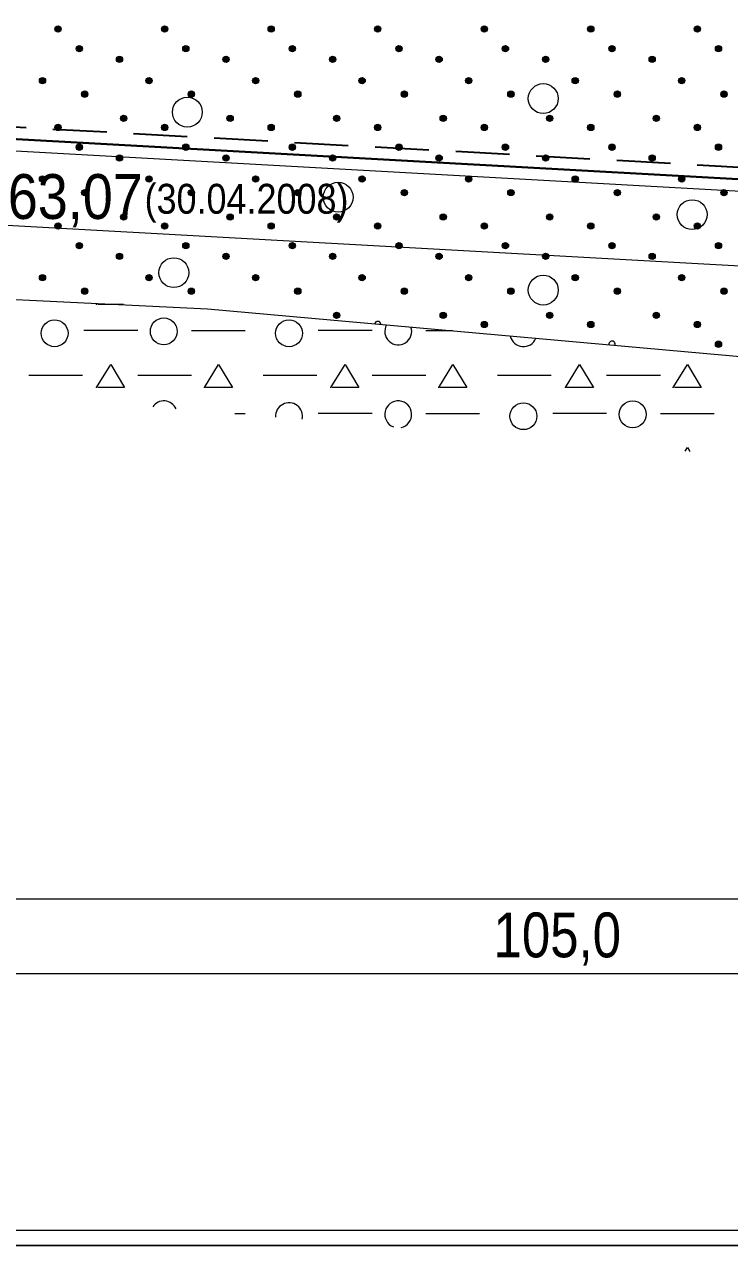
# Model space of a CAD drawing. Extents: x 640104 to 640970, y 6442278 to 6442689.
# Drawn here: x 640426.8 to 640474.1, y 6442282.5 to 6442364.3 of the extents above; entities that cross this region are included whole.
import ezdxf
from ezdxf.enums import TextEntityAlignment as Align

# ---------------------------------------------------------------- set-up
doc = ezdxf.new("R2010")
doc.units = 0
doc.header["$LTSCALE"] = 1.2
doc.linetypes.add('MEDIUM_DASHED', pattern=[4.5, 3, -1.5])
for name, color, linetype, lineweight in [('30', 7, 'Continuous', 13), ('31', 7, 'Continuous', 13), ('34', 7, 'Continuous', 25), ('35', 7, 'Continuous', 35), ('44', 7, 'Continuous', 13), ('46', 7, 'Continuous', 13), ('47', 7, 'Continuous', 13), ('50', 7, 'Continuous', 13)]:
    doc.layers.add(name, color=color, linetype=linetype, lineweight=lineweight)

msp = doc.modelspace()

# ---------------------------------------------------------------- hatches: boundary and pattern name
at = {"layer": '44'}
for points in [[(640429.308, 6442364.001, 1), (640428.888, 6442364.001, 1)], [(640436.441, 6442364.001, 1), (640436.021, 6442364.001, 1)], [(640443.574, 6442364.001, 1), (640443.154, 6442364.001, 1)], [(640450.707, 6442364.001, 1), (640450.287, 6442364.001, 1)], [(640457.84, 6442364.001, 1), (640457.42, 6442364.001, 1)], [(640464.973, 6442364.001, 1), (640464.553, 6442364.001, 1)], [(640472.106, 6442364.001, 1), (640471.686, 6442364.001, 1)], [(640430.727, 6442362.679, 1), (640430.307, 6442362.679, 1)], [(640437.86, 6442362.679, 1), (640437.44, 6442362.679, 1)], [(640444.993, 6442362.679, 1), (640444.573, 6442362.679, 1)], [(640452.126, 6442362.679, 1), (640451.706, 6442362.679, 1)], [(640459.259, 6442362.679, 1), (640458.839, 6442362.679, 1)], [(640466.392, 6442362.679, 1), (640465.972, 6442362.679, 1)], [(640473.525, 6442362.679, 1), (640473.105, 6442362.679, 1)], [(640433.419, 6442361.963, 1), (640432.999, 6442361.963, 1)], [(640440.552, 6442361.963, 1), (640440.132, 6442361.963, 1)], [(640447.685, 6442361.963, 1), (640447.265, 6442361.963, 1)], [(640454.818, 6442361.963, 1), (640454.398, 6442361.963, 1)], [(640461.951, 6442361.963, 1), (640461.531, 6442361.963, 1)], [(640469.084, 6442361.963, 1), (640468.664, 6442361.963, 1)], [(640428.264, 6442360.544, 1), (640427.844, 6442360.544, 1)], [(640435.397, 6442360.544, 1), (640434.977, 6442360.544, 1)], [(640442.53, 6442360.544, 1), (640442.11, 6442360.544, 1)], [(640449.663, 6442360.544, 1), (640449.243, 6442360.544, 1)], [(640456.796, 6442360.544, 1), (640456.376, 6442360.544, 1)], [(640463.929, 6442360.544, 1), (640463.509, 6442360.544, 1)], [(640471.062, 6442360.544, 1), (640470.642, 6442360.544, 1)], [(640431.091, 6442359.636, 1), (640430.671, 6442359.636, 1)], [(640438.224, 6442359.636, 1), (640437.804, 6442359.636, 1)], [(640445.357, 6442359.636, 1), (640444.937, 6442359.636, 1)], [(640452.49, 6442359.636, 1), (640452.07, 6442359.636, 1)], [(640459.623, 6442359.636, 1), (640459.203, 6442359.636, 1)], [(640466.756, 6442359.636, 1), (640466.336, 6442359.636, 1)], [(640473.889, 6442359.636, 1), (640473.469, 6442359.636, 1)], [(640433.693, 6442358.01, 1), (640433.273, 6442358.01, 1)], [(640440.826, 6442358.01, 1), (640440.406, 6442358.01, 1)], [(640447.959, 6442358.01, 1), (640447.539, 6442358.01, 1)], [(640455.092, 6442358.01, 1), (640454.672, 6442358.01, 1)], [(640462.225, 6442358.01, 1), (640461.805, 6442358.01, 1)], [(640469.358, 6442358.01, 1), (640468.938, 6442358.01, 1)], [(640429.308, 6442357.405, 1), (640428.888, 6442357.405, 1)], [(640436.441, 6442357.405, 1), (640436.021, 6442357.405, 1)], [(640443.574, 6442357.405, 1), (640443.154, 6442357.405, 1)], [(640450.707, 6442357.405, 1), (640450.287, 6442357.405, 1)], [(640457.84, 6442357.405, 1), (640457.42, 6442357.405, 1)], [(640464.973, 6442357.405, 1), (640464.553, 6442357.405, 1)], [(640472.106, 6442357.405, 1), (640471.686, 6442357.405, 1)], [(640430.727, 6442356.083, 1), (640430.307, 6442356.083, 1)], [(640433.419, 6442355.367, 1), (640432.999, 6442355.367, 1)], [(640437.86, 6442356.083, 1), (640437.44, 6442356.083, 1)], [(640440.552, 6442355.367, 1), (640440.132, 6442355.367, 1)], [(640444.993, 6442356.083, 1), (640444.573, 6442356.083, 1)], [(640447.685, 6442355.367, 1), (640447.265, 6442355.367, 1)], [(640452.126, 6442356.083, 1), (640451.706, 6442356.083, 1)], [(640454.818, 6442355.367, 1), (640454.398, 6442355.367, 1)], [(640459.259, 6442356.083, 1), (640458.839, 6442356.083, 1)], [(640461.951, 6442355.367, 1), (640461.531, 6442355.367, 1)], [(640466.392, 6442356.083, 1), (640465.972, 6442356.083, 1)], [(640469.084, 6442355.367, 1), (640468.664, 6442355.367, 1)], [(640473.525, 6442356.083, 1), (640473.105, 6442356.083, 1)], [(640428.264, 6442353.948, 1), (640427.844, 6442353.948, 1)], [(640435.397, 6442353.948, 1), (640434.977, 6442353.948, 1)], [(640442.53, 6442353.948, 1), (640442.11, 6442353.948, 1)], [(640449.663, 6442353.948, 1), (640449.243, 6442353.948, 1)], [(640456.796, 6442353.948, 1), (640456.376, 6442353.948, 1)], [(640463.929, 6442353.948, 1), (640463.509, 6442353.948, 1)], [(640471.062, 6442353.948, 1), (640470.642, 6442353.948, 1)], [(640431.091, 6442353.04, 1), (640430.671, 6442353.04, 1)], [(640438.224, 6442353.04, 1), (640437.804, 6442353.04, 1)], [(640445.357, 6442353.04, 1), (640444.937, 6442353.04, 1)], [(640452.49, 6442353.04, 1), (640452.07, 6442353.04, 1)], [(640459.623, 6442353.04, 1), (640459.203, 6442353.04, 1)], [(640466.756, 6442353.04, 1), (640466.336, 6442353.04, 1)], [(640473.889, 6442353.04, 1), (640473.469, 6442353.04, 1)], [(640433.693, 6442351.414, 1), (640433.273, 6442351.414, 1)], [(640440.826, 6442351.414, 1), (640440.406, 6442351.414, 1)], [(640447.959, 6442351.414, 1), (640447.539, 6442351.414, 1)], [(640455.092, 6442351.414, 1), (640454.672, 6442351.414, 1)], [(640462.225, 6442351.414, 1), (640461.805, 6442351.414, 1)], [(640469.358, 6442351.414, 1), (640468.938, 6442351.414, 1)], [(640429.308, 6442350.809, 1), (640428.888, 6442350.809, 1)], [(640436.441, 6442350.809, 1), (640436.021, 6442350.809, 1)], [(640443.574, 6442350.809, 1), (640443.154, 6442350.809, 1)], [(640450.707, 6442350.809, 1), (640450.287, 6442350.809, 1)], [(640457.84, 6442350.809, 1), (640457.42, 6442350.809, 1)], [(640464.973, 6442350.809, 1), (640464.553, 6442350.809, 1)], [(640472.106, 6442350.809, 1), (640471.686, 6442350.809, 1)], [(640430.727, 6442349.487, 1), (640430.307, 6442349.487, 1)], [(640433.419, 6442348.771, 1), (640432.999, 6442348.771, 1)], [(640437.86, 6442349.487, 1), (640437.44, 6442349.487, 1)], [(640440.552, 6442348.771, 1), (640440.132, 6442348.771, 1)], [(640444.993, 6442349.487, 1), (640444.573, 6442349.487, 1)], [(640447.685, 6442348.771, 1), (640447.265, 6442348.771, 1)], [(640452.126, 6442349.487, 1), (640451.706, 6442349.487, 1)], [(640454.818, 6442348.771, 1), (640454.398, 6442348.771, 1)], [(640459.259, 6442349.487, 1), (640458.839, 6442349.487, 1)], [(640461.951, 6442348.771, 1), (640461.531, 6442348.771, 1)], [(640466.392, 6442349.487, 1), (640465.972, 6442349.487, 1)], [(640469.084, 6442348.771, 1), (640468.664, 6442348.771, 1)], [(640473.525, 6442349.487, 1), (640473.105, 6442349.487, 1)], [(640428.264, 6442347.352, 1), (640427.844, 6442347.352, 1)], [(640435.397, 6442347.352, 1), (640434.977, 6442347.352, 1)], [(640442.53, 6442347.352, 1), (640442.11, 6442347.352, 1)], [(640449.663, 6442347.352, 1), (640449.243, 6442347.352, 1)], [(640456.796, 6442347.352, 1), (640456.376, 6442347.352, 1)], [(640463.929, 6442347.352, 1), (640463.509, 6442347.352, 1)], [(640471.062, 6442347.352, 1), (640470.642, 6442347.352, 1)], [(640431.091, 6442346.444, 1), (640430.671, 6442346.444, 1)], [(640438.224, 6442346.444, 1), (640437.804, 6442346.444, 1)], [(640445.357, 6442346.444, 1), (640444.937, 6442346.444, 1)], [(640452.49, 6442346.444, 1), (640452.07, 6442346.444, 1)], [(640459.623, 6442346.444, 1), (640459.203, 6442346.444, 1)], [(640466.756, 6442346.444, 1), (640466.336, 6442346.444, 1)], [(640473.889, 6442346.444, 1), (640473.469, 6442346.444, 1)], [(640447.959, 6442344.818, 1), (640447.539, 6442344.818, 1)], [(640455.092, 6442344.818, 1), (640454.672, 6442344.818, 1)], [(640462.225, 6442344.818, 1), (640461.805, 6442344.818, 1)], [(640469.358, 6442344.818, 1), (640468.938, 6442344.818, 1)], [(640457.84, 6442344.213, 1), (640457.42, 6442344.213, 1)], [(640464.973, 6442344.213, 1), (640464.553, 6442344.213, 1)], [(640472.106, 6442344.213, 1), (640471.686, 6442344.213, 1)], [(640473.525, 6442342.891, 1), (640473.105, 6442342.891, 1)]]:
    msp.add_hatch(color=256, dxfattribs=at).paths.add_polyline_path(points)

# ---------------------------------------------------------------- linework, layer by layer
at = {"layer": '30'}
for p, q in [((640112.44, 6442305.75), (640578.08, 6442305.75)), ((640112.44, 6442300.75), (640578.08, 6442300.75))]:
    msp.add_line(p, q, dxfattribs=at)
at = {"layer": '31'}
msp.add_lwpolyline([(640139.08, 6442391.74), (640152, 6442391.74), (640184.83, 6442387.53), (640224.44, 6442383.27), (640230.93, 6442382.67), (640242.81, 6442381.6), (640246.59, 6442379.93), (640268.17, 6442370.27), (640295.32, 6442359.75), (640299.34, 6442358.9), (640322.09, 6442356.12), (640340.84, 6442354.22), (640374.54, 6442350.71), (640388.93, 6442348.78), (640409.14, 6442347), (640414.32, 6442346.47), (640439.11, 6442345.27), (640478.03, 6442341.77)], dxfattribs=at)
at = {"layer": '34', "lineweight": 13}
msp.add_lwpolyline([(640577.98, 6442339.23), (640519.43, 6442345.64), (640414.37, 6442351.46), (640348.88, 6442353.33)], dxfattribs=at)
at = {"layer": '35', "linetype": 'MEDIUM_DASHED'}
msp.add_lwpolyline([(640518.62, 6442352.3), (640414.65, 6442358.06), (640295.64, 6442361.35)], dxfattribs=at)
at = {"layer": '35', "lineweight": 40}
msp.add_lwpolyline([(640518.52, 6442351.5), (640414.61, 6442357.26), (640295.48, 6442360.55)], dxfattribs=at)
at = {"layer": '35', "lineweight": 13}
msp.add_lwpolyline([(640519.42, 6442350.65), (640414.58, 6442356.46), (640295.32, 6442359.75)], dxfattribs=at)
at = {"layer": '44'}
for centre in [(640429.098, 6442364.001), (640436.231, 6442364.001), (640443.364, 6442364.001), (640450.497, 6442364.001), (640457.63, 6442364.001), (640464.763, 6442364.001), (640471.896, 6442364.001), (640430.517, 6442362.679), (640437.65, 6442362.679), (640444.783, 6442362.679), (640451.916, 6442362.679), (640459.049, 6442362.679), (640466.182, 6442362.679), (640473.315, 6442362.679), (640433.209, 6442361.963), (640440.342, 6442361.963), (640447.475, 6442361.963), (640454.608, 6442361.963), (640461.741, 6442361.963), (640468.874, 6442361.963), (640428.054, 6442360.544), (640435.187, 6442360.544), (640442.32, 6442360.544), (640449.453, 6442360.544), (640456.586, 6442360.544), (640463.719, 6442360.544), (640470.852, 6442360.544), (640430.881, 6442359.636), (640438.014, 6442359.636), (640445.147, 6442359.636), (640452.28, 6442359.636), (640459.413, 6442359.636), (640466.546, 6442359.636), (640473.679, 6442359.636), (640433.483, 6442358.01), (640440.616, 6442358.01), (640447.749, 6442358.01), (640454.882, 6442358.01), (640462.015, 6442358.01), (640469.148, 6442358.01), (640429.098, 6442357.405), (640436.231, 6442357.405), (640443.364, 6442357.405), (640450.497, 6442357.405), (640457.63, 6442357.405), (640464.763, 6442357.405), (640471.896, 6442357.405), (640430.517, 6442356.083), (640433.209, 6442355.367), (640437.65, 6442356.083), (640440.342, 6442355.367), (640444.783, 6442356.083), (640447.475, 6442355.367), (640451.916, 6442356.083), (640454.608, 6442355.367), (640459.049, 6442356.083), (640461.741, 6442355.367), (640466.182, 6442356.083), (640468.874, 6442355.367), (640473.315, 6442356.083), (640428.054, 6442353.948), (640435.187, 6442353.948), (640442.32, 6442353.948), (640449.453, 6442353.948), (640456.586, 6442353.948), (640463.719, 6442353.948), (640470.852, 6442353.948), (640430.881, 6442353.04), (640438.014, 6442353.04), (640445.147, 6442353.04), (640452.28, 6442353.04), (640459.413, 6442353.04), (640466.546, 6442353.04), (640473.679, 6442353.04), (640433.483, 6442351.414), (640440.616, 6442351.414), (640447.749, 6442351.414), (640454.882, 6442351.414), (640462.015, 6442351.414), (640469.148, 6442351.414), (640429.098, 6442350.809), (640436.231, 6442350.809), (640443.364, 6442350.809), (640450.497, 6442350.809), (640457.63, 6442350.809), (640464.763, 6442350.809), (640471.896, 6442350.809), (640430.517, 6442349.487), (640433.209, 6442348.771), (640437.65, 6442349.487), (640440.342, 6442348.771), (640444.783, 6442349.487), (640447.475, 6442348.771), (640451.916, 6442349.487), (640454.608, 6442348.771), (640459.049, 6442349.487), (640461.741, 6442348.771), (640466.182, 6442349.487), (640468.874, 6442348.771), (640473.315, 6442349.487), (640428.054, 6442347.352), (640435.187, 6442347.352), (640442.32, 6442347.352), (640449.453, 6442347.352), (640456.586, 6442347.352), (640463.719, 6442347.352), (640470.852, 6442347.352), (640430.881, 6442346.444), (640438.014, 6442346.444), (640445.147, 6442346.444), (640452.28, 6442346.444), (640459.413, 6442346.444), (640466.546, 6442346.444), (640473.679, 6442346.444), (640447.749, 6442344.818), (640454.882, 6442344.818), (640462.015, 6442344.818), (640469.148, 6442344.818), (640457.63, 6442344.213), (640464.763, 6442344.213), (640471.896, 6442344.213), (640473.315, 6442342.891)]:
    msp.add_circle(centre, 0.21, dxfattribs=at)
for centre, start, end in [((640450.497, 6442344.213), 3.35441, 166.38326), ((640466.182, 6442342.891), 339.68393, 190.05373)]:
    msp.add_arc(centre, 0.21, start, end, dxfattribs=at)
at = {"layer": '46'}
for p, q in [((640433.48, 6442345.54), (640431.75, 6442345.55)), ((640434.43, 6442343.8), (640430.83, 6442343.8)), ((640441.63, 6442343.79), (640438.03, 6442343.79)), ((640450.12, 6442343.8), (640446.52, 6442343.8)), ((640455.5, 6442343.79), (640453.72, 6442343.79)), ((640430.73, 6442340.8), (640427.13, 6442340.8)), ((640438.03, 6442340.8), (640434.43, 6442340.8)), ((640446.43, 6442340.8), (640442.83, 6442340.8)), ((640453.72, 6442340.8), (640450.12, 6442340.8)), ((640462.12, 6442340.8), (640458.52, 6442340.8)), ((640469.42, 6442340.8), (640465.82, 6442340.8)), ((640441.63, 6442338.24), (640440.93, 6442338.24)), ((640450.12, 6442338.25), (640446.52, 6442338.25)), ((640457.32, 6442338.24), (640453.72, 6442338.24)), ((640465.82, 6442338.25), (640462.22, 6442338.25)), ((640473.02, 6442338.24), (640469.42, 6442338.24))]:
    msp.add_line(p, q, dxfattribs=at)
for points in [[(640431.67, 6442345.53), (640431.67, 6442345.55), (640431.72, 6442345.63)], [(640431.67, 6442339.97), (640431.67, 6442340), (640432.62, 6442341.53), (640433.55, 6442339.99), (640431.75, 6442340)], [(640438.89, 6442339.97), (640438.89, 6442340), (640439.84, 6442341.53), (640440.77, 6442339.99), (640438.97, 6442340)], [(640447.36, 6442339.97), (640447.37, 6442340), (640448.31, 6442341.53), (640449.24, 6442339.99), (640447.44, 6442340)], [(640454.58, 6442339.97), (640454.59, 6442340), (640455.53, 6442341.53), (640456.46, 6442339.99), (640454.66, 6442340)], [(640463.06, 6442339.97), (640463.06, 6442340), (640464.01, 6442341.53), (640464.94, 6442339.99), (640463.14, 6442340)], [(640470.28, 6442339.97), (640470.28, 6442340), (640471.23, 6442341.53), (640472.16, 6442339.99), (640470.36, 6442340)], [(640471.08, 6442335.73), (640471.23, 6442335.97), (640471.39, 6442335.7)]]:
    msp.add_lwpolyline(points, dxfattribs=at)
for centre in [(640428.864, 6442343.626), (640436.177, 6442343.748), (640444.559, 6442343.626), (640460.254, 6442338.072), (640467.567, 6442338.194)]:
    msp.add_circle(centre, 0.9, dxfattribs=at)
for centre, start, end in [((640451.872, 6442343.748), 150.56178, 19.17589), ((640460.254, 6442343.626), 191.49631, 338.24136), ((640436.177, 6442338.194), 24.57571, 145.89701), ((640444.559, 6442338.072), 346.71377, 183.75895), ((640451.872, 6442338.194), 281.84927, 248.62344)]:
    msp.add_arc(centre, 0.9, start, end, dxfattribs=at)
at = {"layer": '47'}
for centre in [(640461.581, 6442359.338), (640437.752, 6442358.431), (640447.853, 6442352.733), (640471.553, 6442351.567), (640436.845, 6442347.682), (640461.581, 6442346.516)]:
    msp.add_circle(centre, 1, dxfattribs=at)
at = {"layer": '50', "lineweight": 25}
msp.add_lwpolyline([(640103.56, 6442688.99), (640970.3, 6442688.99), (640970.3, 6442282.54), (640103.56, 6442282.54)], close=True, dxfattribs=at)
at = {"layer": '50'}
msp.add_lwpolyline([(640104.56, 6442687.99), (640969.3, 6442687.99), (640969.3, 6442283.54), (640104.56, 6442283.54)], close=True, dxfattribs=at)

# ---------------------------------------------------------------- texts
at = {"layer": '30', "width": 0.85}
msp.add_text('105,0', height=3, dxfattribs=at).set_placement((640462.52, 6442301.84), align=Align.CENTER)
at = {"layer": '34', "width": 0.9}
for s, height, p in [('63,07', 3, (640430.25, 6442351.28)), ('(30.04.2008)', 2, (640441.715, 6442351.63))]:
    msp.add_text(s, height=height, dxfattribs=at).set_placement(p, align=Align.CENTER)

doc.saveas('drawing.dxf')
